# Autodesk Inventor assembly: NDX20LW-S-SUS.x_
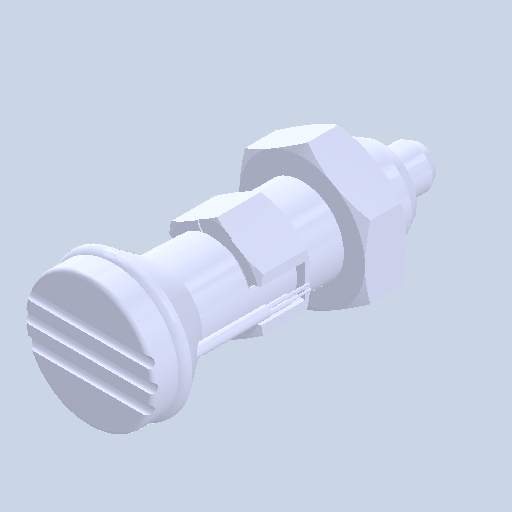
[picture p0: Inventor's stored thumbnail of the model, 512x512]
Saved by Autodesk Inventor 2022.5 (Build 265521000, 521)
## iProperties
Created: 2024-05
Part Number: NDX20LW-S-SUS.x_
Document SubType Name: Assembly
Designer: ImaoCorp
Author: ImaoCorp
Sending System: SOLIDWORKS 2022-2022290
MC: AMD64
MC_MODEL: Intel64 Family 6 Model 60 Stepping 3, GenuineIntel
OS: Windows_NT
FRU: Parasolid Version 33.1, build 260,  4-25-2022
FORMAT: text
GUISE: transmit
KEY: FILENDX20LW-S-SUS.x_t
DATE: Tue May 21 08:47:33 2024
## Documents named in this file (3)
- X:\14_SW2022-Inv2022\保留中\kipp\KME_データ\n\ndx20lw-s-sus\NDX20LW-S-SUS.x_.iam
- X:\14_SW2022-Inv2022\保留中\kipp\KME_データ\n\ndx20lw-s-sus\NDX20LW-S-SUS_01.ipt
- X:\14_SW2022-Inv2022\保留中\kipp\KME_データ\n\ndx20lw-s-sus\NDX20LW-S-SUS_02.ipt
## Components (2 placed, 2 different names)
1. NDX20LW-S-SUS_01
2. NDX20LW-S-SUS_02
